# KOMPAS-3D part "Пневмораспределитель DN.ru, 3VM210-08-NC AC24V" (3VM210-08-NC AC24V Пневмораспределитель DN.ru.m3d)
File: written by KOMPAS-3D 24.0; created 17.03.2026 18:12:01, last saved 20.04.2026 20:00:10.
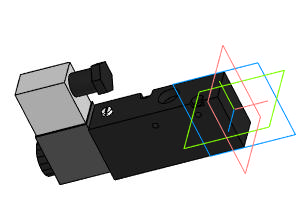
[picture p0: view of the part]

Document properties: Автор: R2D2; Полное имя файла: E:\Работа\Зайцев\Аксессуары для пневмоприводов\Пневмораспределители DN.ru\3VM210-08-NC Пневмораспределитель DN.RU\AC24V\3VM210-08-NC AC24V Пневмораспределитель DN.ru.m3d

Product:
- Part/product: Пневмораспределитель DN.ru  | designation 3VM210-08-NC AC24V
    Масса: 0.3
    Раздел спецификации: Прочие изделия
    Примечание: D290-00375

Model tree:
1. Операция без истории:1

Expressions: 3VM210-08-NC AC24V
